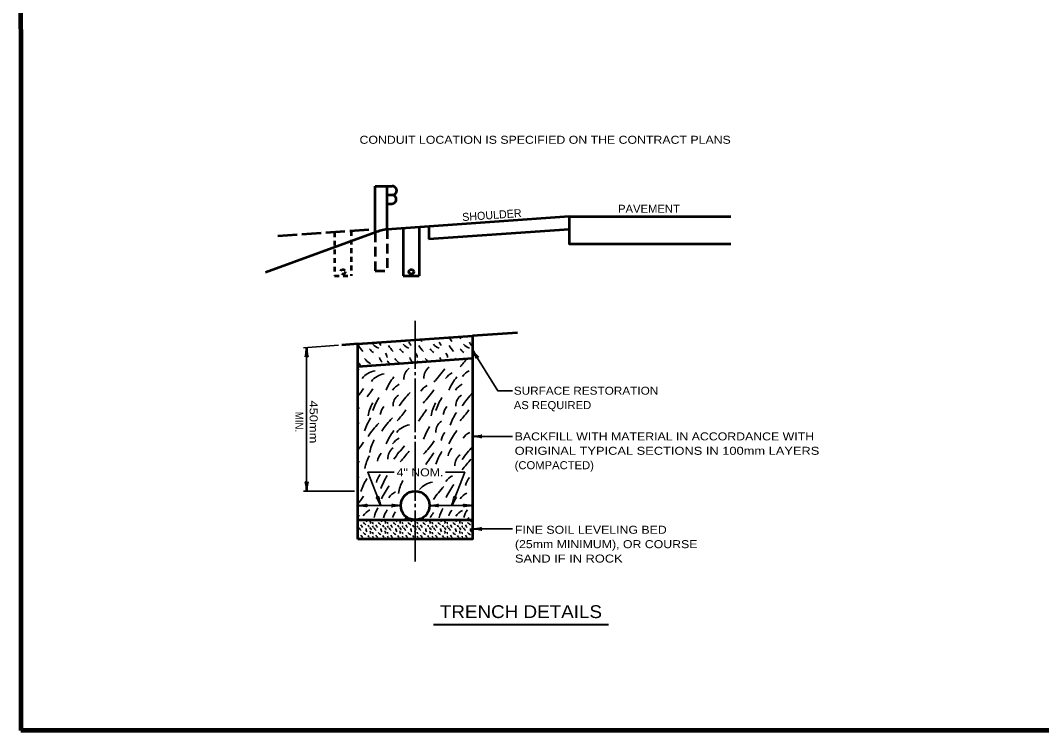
# Model space of a CAD drawing. Extents: x -50 to 806, y -9 to 535.
# Drawn here: x 7.5 to 390.3, y 2.8 to 269 of the extents above; entities that cross this region are included whole.
import ezdxf
from ezdxf.enums import TextEntityAlignment as Align

# ---------------------------------------------------------------- set-up
doc = ezdxf.new("R2010")
doc.units = 0
doc.header["$LTSCALE"] = 1.2
for name, pattern in [('LONG_DASHED', [7.5, 6, -1.5]), ('MEDIUM_DASHED', [4.5, 3, -1.5]), ('SHORT_DASHED', [2.7, 1.5, -1.2])]:
    doc.linetypes.add(name, pattern=pattern)
doc.layers.add('1', color=7, linetype='Continuous', lineweight=35)

msp = doc.modelspace()

# ---------------------------------------------------------------- linework, layer by layer
at = {"layer": '1', "lineweight": 53}
for p, q in [((140.511, 189.479), (140.511, 206.879)), ((140.511, 206.879), (146.811, 206.879)), ((145.011, 203.579), (146.811, 203.579)), ((145.011, 200.279), (146.811, 200.279)), ((213.244, 195.451), (273.844, 195.451)), ((157.011, 191.519), (157.011, 173.279)), ((160.611, 191.77), (160.611, 186.97)), ((140.511, 189.479), (99.352, 174.499)), ((151.011, 191.099), (151.011, 173.279)), ((213.244, 190.651), (160.611, 186.97)), ((151.011, 173.279), (157.011, 173.279)), ((133.917, 147.736), (177.012, 150.749)), ((193.771, 151.921), (177.012, 150.749)), ((177.012, 150.749), (177.012, 142.329)), ((133.917, 147.736), (127.932, 147.317)), ((133.917, 139.315), (133.917, 147.736))]:
    msp.add_line(p, q, dxfattribs=at)
at = {"layer": '1', "linetype": 'LONG_DASHED', "lineweight": 53}
msp.add_line((138.116, 190.512), (103.401, 188.085), dxfattribs=at)
at = {"layer": '1', "linetype": 'SHORT_DASHED', "lineweight": 53}
msp.add_line((131.511, 190.05), (131.511, 173.279), dxfattribs=at)
at = {"layer": '1', "linetype": 'MEDIUM_DASHED', "lineweight": 53}
for p, q in [((140.511, 189.479), (140.511, 175.079)), ((145.011, 190.679), (145.011, 175.079)), ((140.511, 175.079), (145.011, 175.079))]:
    msp.add_line(p, q, dxfattribs=at)
at = {"layer": '1'}
for p, q in [((155.464, 138.357), (155.464, 156.442)), ((126.735, 147.233), (113.567, 146.313)), ((114.767, 92.536), (114.767, 146.397)), ((155.464, 135.957), (155.464, 137.157)), ((155.464, 114.604), (155.464, 134.757)), ((155.464, 112.204), (155.464, 113.404)), ((177.012, 113.049), (192.016, 113.049)), ((155.464, 92.536), (155.464, 111.004)), ((132.717, 92.536), (113.567, 92.536)), ((155.464, 88.936), (155.464, 92.536)), ((150.064, 87.136), (133.917, 87.136)), ((155.464, 86.536), (155.464, 87.736)), ((155.464, 81.736), (155.464, 85.336)), ((160.864, 87.136), (177.012, 87.136)), ((155.464, 66.136), (155.464, 81.736)), ((177.012, 78.369), (192.016, 78.369))]:
    msp.add_line(p, q, dxfattribs=at)
at = {"layer": '1', "lineweight": 40}
msp.add_line((162.365, 42.591), (228.01, 42.591), dxfattribs=at)
at = {"layer": '1', "lineweight": 158}
msp.add_line((799.155, 2.763), (7.555, 2.763), dxfattribs=at)
msp.add_lwpolyline([(799.155, 528.863), (7.455, 528.763), (7.555, 2.763)], dxfattribs=at)
at = {"layer": '1', "lineweight": 53}
for points in [[(213.244, 195.451), (145.011, 190.679), (145.011, 206.879)], [(213.244, 195.451), (213.244, 185.251), (273.844, 185.251)], [(133.917, 81.736), (133.917, 139.315), (177.012, 142.329), (177.012, 81.736)]]:
    msp.add_lwpolyline(points, dxfattribs=at)
at = {"layer": '1', "linetype": 'SHORT_DASHED', "lineweight": 53}
msp.add_lwpolyline([(125.211, 189.609), (125.211, 173.279), (131.511, 173.279)], dxfattribs=at)
at = {"layer": '1'}
for points in [[(177.012, 145.448), (186.417, 130.174), (192.016, 130.174)], [(147.596, 99.63), (137.691, 99.63), (142.547, 87.136)], [(166.855, 99.63), (174.075, 99.63), (169.219, 87.136)]]:
    msp.add_lwpolyline(points, dxfattribs=at)
at = {"layer": '1', "lineweight": 53}
msp.add_lwpolyline([(133.917, 74.536), (133.917, 81.736), (177.012, 81.736), (177.012, 74.536)], close=True, dxfattribs=at)
at = {"layer": '1', "linetype": 'SHORT_DASHED', "lineweight": 53}
msp.add_circle((128.361, 174.779), 0.9, dxfattribs=at)
at = {"layer": '1', "lineweight": 53}
for centre, radius in [((154.011, 174.779), 0.9), ((155.464, 87.136), 5.4)]:
    msp.add_circle(centre, radius, dxfattribs=at)
for centre, radius, start, end in [((146.885, 205.229), 1.652, 267.42897, 92.57103), ((146.736, 201.929), 1.652, 267.42897, 92.57103), ((146.313, 176.757), 13.983, 95.34535, 114.51748)]:
    msp.add_arc(centre, radius, start, end, dxfattribs=at)
at = {"layer": '1'}
for centre, radius, start, end in [((135.888, 133.103), 26.988, 35.21542, 37.08999), ((147.216, 133.103), 26.988, 35.21542, 39.11596), ((176.211, 155.733), 6.947, 230.36768, 239.42983), ((180.068, 153.138), 4.111, 215.86437, 221.98733), ((142.651, 152), 9.765, 210.01676, 226.2782), ((142.186, 148.278), 4.499, 212.31381, 237.6655), ((143.133, 150.65), 4.662, 221.18175, 253.32925), ((137.217, 144.628), 5.908, 24.88286, 38.30577), ((153.979, 152), 9.765, 210.01676, 226.2782), ((153.514, 148.278), 4.499, 212.31381, 237.6655), ((154.461, 150.65), 4.662, 221.18175, 253.32925), ((148.545, 144.628), 5.908, 24.88286, 39.11285), ((165.307, 152), 9.765, 210.01676, 226.2782), ((164.842, 148.278), 4.499, 212.31381, 237.6655), ((165.789, 150.65), 4.662, 221.18175, 253.32925), ((159.873, 144.628), 5.908, 24.88286, 39.11285), ((176.635, 152), 9.765, 210.01676, 226.2782), ((176.17, 148.278), 4.499, 212.31381, 237.6655), ((177.117, 150.65), 4.662, 221.18175, 253.32925), ((171.201, 144.628), 5.908, 24.88286, 39.11285), ((142.227, 146.277), 6.947, 214.79584, 239.42983), ((146.084, 143.682), 4.111, 194.9284, 222.27877), ((142.459, 142.692), 2.446, 358.18251, 41.77121), ((153.555, 146.277), 6.947, 214.79584, 237.37734), ((157.412, 143.682), 4.111, 194.9284, 222.27877), ((153.787, 142.692), 2.446, 358.18251, 41.77121), ((164.883, 146.277), 6.947, 214.79584, 227.53781), ((168.74, 143.682), 4.111, 194.9284, 211.96003), ((165.115, 142.692), 2.446, 358.18251, 41.77121), ((176.211, 146.277), 6.947, 214.79584, 219.10556), ((146.654, 163.184), 35.169, 316.85332, 323.32436), ((180.068, 143.682), 4.111, 194.9284, 200.0611), ((113.232, 123.647), 26.988, 35.71347, 39.96501), ((135.438, 130.94), 7.331, 97.86047, 101.97732), ((124.56, 123.647), 26.988, 37.70729, 41.08213), ((156.083, 134.668), 4.834, 125.55617, 183.03926), ((135.888, 123.647), 26.988, 39.74853, 41.08213), ((163.56, 135.035), 4.834, 125.55617, 183.03926), ((174.709, 138.996), 13.418, 170.36149, 171.43197), ((137.106, 158.231), 35.483, 315.74458, 326.0875), ((172.55, 140.141), 6.727, 167.85392, 168.69132), ((141.424, 130.346), 7.331, 97.86047, 142.43933), ((144.842, 129.231), 7.331, 97.86047, 142.43933), ((170.483, 118.385), 28.609, 143.51724, 155.10041), ((172.362, 130.996), 6.628, 116.78814, 145.60117), ((194.075, 118.385), 28.609, 143.51724, 155.10041), ((178.676, 131.768), 6.628, 116.78814, 145.60117), ((182.622, 130.94), 7.331, 139.93842, 142.43933), ((106.695, 150.848), 35.483, 320.10204, 326.0875), ((110.186, 150.7), 35.483, 320.10204, 326.0875), ((152.484, 126.686), 6.628, 116.78814, 145.60117), ((163.002, 126.24), 6.628, 116.78814, 145.60117), ((133.035, 150.328), 35.483, 315.74458, 326.0875), ((176.076, 126.686), 6.628, 116.78814, 145.60117), ((169.626, 111.257), 32.207, 149.42797, 158.94436), ((151.998, 124.636), 4.834, 125.55617, 183.03926), ((180.074, 103.819), 36.934, 135.94755, 145.88313), ((193.218, 111.257), 32.207, 149.42797, 158.94436), ((175.59, 124.636), 4.834, 125.55617, 183.03926), ((203.666, 103.819), 36.934, 136.19292, 145.88313), ((-19.32, 225.043), 184.032, 326.37338, 326.66613), ((151.117, 118.812), 13.418, 149.50579, 171.43197), ((148.958, 119.957), 6.727, 140.62862, 168.69132), ((123.062, 143), 35.169, 316.85332, 325.30832), ((5.906, 224.225), 184.032, 325.03164, 326.66613), ((174.709, 118.812), 13.418, 149.50579, 171.43197), ((172.55, 119.957), 6.727, 140.62862, 168.69132), ((146.654, 143), 35.169, 316.85332, 325.30832), ((166.506, 103.586), 32.207, 149.42797, 158.94436), ((173.485, 94.317), 36.934, 135.94755, 145.88313), ((168.087, 114.81), 4.834, 125.55617, 183.03926), ((198.641, 105.684), 32.207, 149.42797, 158.94436), ((135.438, 110.756), 7.331, 97.86047, 101.97732), ((168.359, 92.311), 36.934, 135.94755, 145.88313), ((170.483, 98.201), 28.609, 143.51724, 155.10041), ((154.35, 110.088), 7.331, 97.86047, 142.43933), ((188.612, 100.39), 32.207, 149.42797, 158.94436), ((194.075, 98.201), 28.609, 143.51724, 155.10041), ((182.622, 110.756), 7.331, 139.93842, 142.43933), ((151.711, 105.019), 13.418, 149.50579, 171.43197), ((152.484, 106.502), 6.628, 116.78814, 145.60117), ((133.184, 131.185), 35.483, 315.74458, 326.0875), ((171.807, 110.251), 6.727, 140.62862, 168.69132), ((178.887, 108.643), 6.628, 116.78814, 145.60117), ((106.695, 130.664), 35.483, 320.10204, 326.0875), ((150.026, 104.83), 4.834, 125.55617, 183.03926), ((178.06, 83.803), 36.934, 135.94755, 145.88313), ((124.237, 127.558), 35.169, 316.85332, 325.30832), ((193.218, 91.073), 32.207, 149.42797, 158.94436), ((174.396, 104.39), 6.727, 140.62862, 168.69132), ((203.666, 83.635), 36.934, 136.19292, 145.88313), ((-19.32, 204.859), 184.032, 326.37338, 326.66613), ((149.894, 98.975), 13.418, 149.50579, 171.43197), ((147.909, 102.459), 6.727, 140.62862, 168.69132), ((8.656, 208.02), 184.032, 325.03164, 326.66613), ((175.17, 102.227), 4.834, 125.55617, 183.03926), ((147.367, 124.578), 35.169, 316.85332, 325.30832), ((135.438, 90.572), 7.331, 97.86047, 101.97732), ((165.097, 80.882), 32.207, 149.42797, 158.94436), ((147.531, 94.443), 6.727, 140.62862, 168.69132), ((172.701, 81.999), 32.207, 149.42797, 158.94436), ((162.444, 89.697), 13.418, 149.50579, 171.43197), ((162.914, 88.619), 7.331, 97.86047, 142.43933), ((172.475, 92.365), 6.628, 116.78814, 145.60117), ((180.989, 93.37), 6.727, 140.62862, 168.69132), ((168.763, 77.556), 28.609, 143.51724, 155.10041), ((151.015, 86.318), 6.628, 116.78814, 145.60117), ((192.928, 68.728), 36.934, 136.19292, 145.88313), ((193.026, 78.059), 28.609, 143.51724, 155.10041), ((182.622, 90.572), 7.331, 139.93842, 142.43933), ((106.695, 110.48), 35.483, 320.10204, 326.0875), ((177.796, 85.857), 6.628, 116.78814, 145.60117), ((141.415, 79.556), 6.628, 116.78814, 145.60117), ((153.048, 79.41), 13.418, 149.50579, 165.79857), ((150.221, 81.196), 6.727, 140.62862, 168.69132), ((153.341, 80.481), 6.727, 140.62862, 161.39272), ((8.589, 185.627), 184.032, 325.98885, 326.66613), ((177.457, 79.261), 13.418, 149.50579, 165.79857), ((174.407, 81.075), 6.727, 140.62862, 161.39272), ((176.224, 79.407), 6.628, 116.78814, 145.60117), ((180.307, 81.27), 6.727, 140.62862, 168.69132), ((-19.32, 184.675), 184.032, 326.37338, 326.66613), ((134.174, 80.728), 0.313, 214.78265, 277.12922), ((137.018, 83.766), 2.829, 225.86486, 230.55554), ((139.425, 83.834), 4.574, 221.45311, 238.05569), ((139.921, 82.496), 2.912, 195.13344, 210.03985), ((138.124, 80.823), 0.598, 317.34474, 61.57588), ((139.766, 80.728), 0.313, 150.23947, 277.12922), ((142.61, 83.766), 2.829, 225.86486, 230.55554), ((145.017, 83.834), 4.574, 221.45311, 238.05569), ((145.513, 82.496), 2.912, 195.13344, 210.03985), ((143.716, 80.823), 0.598, 317.34474, 61.57588), ((145.358, 80.728), 0.313, 150.23947, 277.12922), ((148.202, 83.766), 2.829, 225.86486, 230.55554), ((150.609, 83.834), 4.574, 221.45311, 238.05569), ((151.105, 82.496), 2.912, 195.13344, 210.03985), ((149.308, 80.823), 0.598, 317.34474, 61.57588), ((150.95, 80.728), 0.313, 150.23947, 277.12922), ((123.062, 102.632), 35.169, 323.54678, 325.30832), ((153.794, 83.766), 2.829, 225.86486, 230.55554), ((156.201, 83.834), 4.574, 221.45311, 238.05569), ((156.697, 82.496), 2.912, 195.13344, 210.03985), ((154.9, 80.823), 0.598, 317.34474, 61.57588), ((156.542, 80.728), 0.313, 150.23947, 277.12922), ((159.386, 83.766), 2.829, 225.86486, 230.55554), ((161.793, 83.834), 4.574, 221.45311, 238.05569), ((162.289, 82.496), 2.912, 195.13344, 210.03985), ((160.492, 80.823), 0.598, 317.34474, 61.57588), ((162.134, 80.728), 0.313, 150.23947, 277.12922), ((164.978, 83.766), 2.829, 225.86486, 230.55554), ((167.385, 83.834), 4.574, 221.45311, 238.05569), ((167.881, 82.496), 2.912, 195.13344, 210.03985), ((166.084, 80.823), 0.598, 317.34474, 61.57588), ((167.726, 80.728), 0.313, 150.23947, 277.12922), ((170.57, 83.766), 2.829, 225.86486, 230.55554), ((172.977, 83.834), 4.574, 221.45311, 238.05569), ((173.473, 82.496), 2.912, 195.13344, 210.03985), ((171.676, 80.823), 0.598, 317.34474, 61.57588), ((173.318, 80.728), 0.313, 150.23947, 277.12922), ((176.162, 83.766), 2.829, 225.86486, 230.55554), ((146.654, 102.632), 35.169, 323.54678, 325.30832), ((178.569, 83.834), 4.574, 221.45311, 238.05569), ((179.065, 82.496), 2.912, 195.13344, 210.03985), ((134.51, 79.474), 0.608, 192.65873, 240.71511), ((134.174, 76.936), 0.313, 214.78265, 277.12922), ((137.018, 79.974), 2.829, 204.56614, 230.55554), ((138.423, 81.388), 3.612, 204.77096, 222.58913), ((139.425, 80.042), 4.574, 221.45311, 238.05569), ((139.921, 78.704), 2.912, 182.72927, 210.03985), ((138.531, 79.791), 0.746, 185.54013, 248.19074), ((138.124, 77.031), 0.598, 317.34474, 61.57588), ((139.181, 78.753), 0.576, 159.67517, 270.27989), ((139.766, 76.936), 0.313, 150.23947, 277.12922), ((140.102, 79.474), 0.608, 178.77007, 240.71511), ((142.61, 79.974), 2.829, 204.56614, 230.55554), ((144.015, 81.388), 3.612, 204.77096, 222.58913), ((145.017, 80.042), 4.574, 221.45311, 238.05569), ((145.513, 78.704), 2.912, 182.72927, 210.03985), ((144.123, 79.791), 0.746, 185.54013, 248.19074), ((143.716, 77.031), 0.598, 317.34474, 61.57588), ((144.773, 78.753), 0.576, 159.67517, 270.27989), ((145.358, 76.936), 0.313, 150.23947, 277.12922), ((145.694, 79.474), 0.608, 178.77007, 240.71511), ((148.202, 79.974), 2.829, 204.56614, 230.55554), ((149.607, 81.388), 3.612, 204.77096, 222.58913), ((150.609, 80.042), 4.574, 221.45311, 238.05569), ((151.105, 78.704), 2.912, 182.72927, 210.03985), ((149.715, 79.791), 0.746, 185.54013, 248.19074), ((149.308, 77.031), 0.598, 317.34474, 61.57588), ((150.365, 78.753), 0.576, 159.67517, 270.27989), ((150.95, 76.936), 0.313, 150.23947, 277.12922), ((151.286, 79.474), 0.608, 178.77007, 240.71511), ((153.794, 79.974), 2.829, 204.56614, 230.55554), ((155.199, 81.388), 3.612, 204.77096, 222.58913), ((156.201, 80.042), 4.574, 221.45311, 238.05569), ((156.697, 78.704), 2.912, 182.72927, 210.03985), ((155.307, 79.791), 0.746, 185.54013, 248.19074), ((154.9, 77.031), 0.598, 317.34474, 61.57588), ((155.957, 78.753), 0.576, 159.67517, 270.27989), ((156.542, 76.936), 0.313, 150.23947, 277.12922), ((156.878, 79.474), 0.608, 178.77007, 240.71511), ((159.386, 79.974), 2.829, 204.56614, 230.55554), ((160.791, 81.388), 3.612, 204.77096, 222.58913), ((161.793, 80.042), 4.574, 221.45311, 238.05569), ((162.289, 78.704), 2.912, 182.72927, 210.03985), ((160.899, 79.791), 0.746, 185.54013, 248.19074), ((160.492, 77.031), 0.598, 317.34474, 61.57588), ((161.549, 78.753), 0.576, 159.67517, 270.27989), ((162.134, 76.936), 0.313, 150.23947, 277.12922), ((162.47, 79.474), 0.608, 178.77007, 240.71511), ((164.978, 79.974), 2.829, 204.56614, 230.55554), ((166.383, 81.388), 3.612, 204.77096, 222.58913), ((167.385, 80.042), 4.574, 221.45311, 238.05569), ((167.881, 78.704), 2.912, 182.72927, 210.03985), ((166.491, 79.791), 0.746, 185.54013, 248.19074), ((166.084, 77.031), 0.598, 317.34474, 61.57588), ((167.141, 78.753), 0.576, 159.67517, 270.27989), ((167.726, 76.936), 0.313, 150.23947, 277.12922), ((168.062, 79.474), 0.608, 178.77007, 240.71511), ((170.57, 79.974), 2.829, 204.56614, 230.55554), ((171.975, 81.388), 3.612, 204.77096, 222.58913), ((172.977, 80.042), 4.574, 221.45311, 238.05569), ((173.473, 78.704), 2.912, 182.72927, 210.03985), ((172.083, 79.791), 0.746, 185.54013, 248.19074), ((171.676, 77.031), 0.598, 317.34474, 61.57588), ((172.733, 78.753), 0.576, 159.67517, 270.27989), ((173.318, 76.936), 0.313, 150.23947, 277.12922), ((173.654, 79.474), 0.608, 178.77007, 240.71511), ((176.162, 79.974), 2.829, 204.56614, 230.55554), ((177.567, 81.388), 3.612, 204.77096, 222.58913), ((178.569, 80.042), 4.574, 221.45311, 238.05569), ((179.065, 78.704), 2.912, 182.72927, 210.03985), ((177.675, 79.791), 0.746, 185.54013, 207.30991), ((134.51, 75.682), 0.608, 192.65873, 240.71511), ((137.018, 76.182), 2.829, 204.56614, 215.58842), ((138.423, 77.596), 3.612, 204.77096, 222.58913), ((139.921, 74.912), 2.912, 182.72927, 187.42205), ((138.531, 75.999), 0.746, 185.54013, 248.19074), ((139.181, 74.961), 0.576, 159.67517, 227.62772), ((140.102, 75.682), 0.608, 178.77007, 240.71511), ((142.61, 76.182), 2.829, 204.56614, 215.58842), ((144.015, 77.596), 3.612, 204.77096, 222.58913), ((145.513, 74.912), 2.912, 182.72927, 187.42205), ((144.123, 75.999), 0.746, 185.54013, 248.19074), ((144.773, 74.961), 0.576, 159.67517, 227.62772), ((145.694, 75.682), 0.608, 178.77007, 240.71511), ((148.202, 76.182), 2.829, 204.56614, 215.58842), ((149.607, 77.596), 3.612, 204.77096, 222.58913), ((151.105, 74.912), 2.912, 182.72927, 187.42205), ((149.715, 75.999), 0.746, 185.54013, 248.19074), ((150.365, 74.961), 0.576, 159.67517, 227.62772), ((151.286, 75.682), 0.608, 178.77007, 240.71511), ((153.794, 76.182), 2.829, 204.56614, 215.58842), ((155.199, 77.596), 3.612, 204.77096, 222.58913), ((156.697, 74.912), 2.912, 182.72927, 187.42205), ((155.307, 75.999), 0.746, 185.54013, 248.19074), ((155.957, 74.961), 0.576, 159.67517, 227.62772), ((156.878, 75.682), 0.608, 178.77007, 240.71511), ((159.386, 76.182), 2.829, 204.56614, 215.58842), ((160.791, 77.596), 3.612, 204.77096, 222.58913), ((162.289, 74.912), 2.912, 182.72927, 187.42205), ((160.899, 75.999), 0.746, 185.54013, 248.19074), ((161.549, 74.961), 0.576, 159.67517, 227.62772), ((162.47, 75.682), 0.608, 178.77007, 240.71511), ((164.978, 76.182), 2.829, 204.56614, 215.58842), ((166.383, 77.596), 3.612, 204.77096, 222.58913), ((167.881, 74.912), 2.912, 182.72927, 187.42205), ((166.491, 75.999), 0.746, 185.54013, 248.19074), ((167.141, 74.961), 0.576, 159.67517, 227.62772), ((168.062, 75.682), 0.608, 178.77007, 240.71511), ((170.57, 76.182), 2.829, 204.56614, 215.58842), ((171.975, 77.596), 3.612, 204.77096, 222.58913), ((173.473, 74.912), 2.912, 182.72927, 187.42205), ((172.083, 75.999), 0.746, 185.54013, 248.19074), ((172.733, 74.961), 0.576, 159.67517, 227.62772), ((173.654, 75.682), 0.608, 178.77007, 240.71511), ((176.162, 76.182), 2.829, 204.56614, 215.58842), ((177.567, 77.596), 3.612, 204.77096, 222.58913), ((179.065, 74.912), 2.912, 182.72927, 187.42205), ((177.675, 75.999), 0.746, 185.54013, 207.30991)]:
    msp.add_arc(centre, radius, start, end, dxfattribs=at)
at = {"layer": '1', "lineweight": 40}
for centre, major_axis, ratio, start_param, end_param in [((114.513, 145.052), (0.211, 2.108), 0.07063, 3.1407148, 5.41811), ((115.098, 145.087), (-0.187, 2.143), 0.122415, 0.8963533, 3.1415927), ((177.501, 144.17), (0.926, -1.905), 0.07063, 6.2823074, 8.5597026), ((177.501, 144.17), (0.926, -1.905), 0.07063, 6.2823074, 8.5597026), ((177.981, 144.507), (-1.283, 1.726), 0.122415, 0.8963533, 3.1415927), ((177.981, 144.507), (-1.283, 1.726), 0.122415, 0.8963533, 3.1415927), ((178.356, 112.795), (-2.108, 0.211), 0.07063, 3.1407148, 5.41811), ((178.356, 112.795), (-2.108, 0.211), 0.07063, 3.1407148, 5.41811), ((178.321, 113.381), (-2.143, -0.187), 0.122415, 0.8963533, 3.1415927), ((178.321, 113.381), (-2.143, -0.187), 0.122415, 0.8963533, 3.1415927), ((114.435, 93.845), (0.187, -2.143), 0.122415, 0.8963533, 3.1415927), ((115.021, 93.88), (-0.211, -2.108), 0.07063, 3.1407148, 5.41811), ((141.823, 88.297), (0.96, -1.888), 0.07063, 0.8650754, 3.1424706), ((142.381, 88.476), (0.602, -2.065), 0.122415, 3.1415927, 5.386832), ((169.384, 88.476), (-0.602, -2.065), 0.122415, 0.8963533, 3.1415927), ((169.942, 88.297), (-0.96, -1.888), 0.07063, 3.1407148, 5.41811), ((135.226, 87.467), (-2.143, -0.187), 0.122415, 0.8963533, 3.1415927), ((135.226, 87.467), (-2.143, -0.187), 0.122415, 0.8963533, 3.1415927), ((135.262, 86.882), (-2.108, 0.211), 0.07063, 3.1407148, 5.41811), ((135.262, 86.882), (-2.108, 0.211), 0.07063, 3.1407148, 5.41811), ((148.755, 86.804), (2.143, 0.187), 0.122415, 0.8963533, 3.1415927), ((148.755, 86.804), (2.143, 0.187), 0.122415, 0.8963533, 3.1415927), ((148.72, 87.39), (2.108, -0.211), 0.07063, 3.1407148, 5.41811), ((148.72, 87.39), (2.108, -0.211), 0.07063, 3.1407148, 5.41811), ((162.209, 86.882), (-2.108, 0.211), 0.07063, 3.1407148, 5.41811), ((162.209, 86.882), (-2.108, 0.211), 0.07063, 3.1407148, 5.41811), ((162.174, 87.467), (-2.143, -0.187), 0.122415, 0.8963533, 3.1415927), ((162.174, 87.467), (-2.143, -0.187), 0.122415, 0.8963533, 3.1415927), ((175.702, 86.804), (2.143, 0.187), 0.122415, 0.8963533, 3.1415927), ((175.667, 87.39), (2.108, -0.211), 0.07063, 3.1407148, 5.41811), ((178.356, 78.115), (-2.108, 0.211), 0.07063, 3.1407148, 5.41811), ((178.356, 78.115), (-2.108, 0.211), 0.07063, 3.1407148, 5.41811), ((178.321, 78.701), (-2.143, -0.187), 0.122415, 0.8963533, 3.1415927), ((178.321, 78.701), (-2.143, -0.187), 0.122415, 0.8963533, 3.1415927)]:
    msp.add_ellipse(centre, major_axis=major_axis, ratio=ratio, start_param=start_param, end_param=end_param, dxfattribs=at)

# ---------------------------------------------------------------- texts
at = {"layer": '1'}
for s, height, width, p in [('CONDUIT LOCATION IS SPECIFIED ON THE CONTRACT PLANS', 3, 1.15, (134.604, 222.762)), ('PAVEMENT', 3, 1.05, (231.542, 196.891)), ('SURFACE RESTORATION', 3, 1.1, (192.446, 128.682)), ('AS REQUIRED', 3, 1.05, (192.446, 123.282)), ('BACKFILL WITH MATERIAL IN ACCORDANCE WITH', 3, 1.15, (192.769, 111.557)), ('ORIGINAL TYPICAL SECTIONS IN 100mm LAYERS', 3, 1.2, (192.769, 106.157)), ('(COMPACTED)', 3, 1.05, (192.769, 100.757)), ('4" NOM.', 3, 1.15, (148.518, 98.079)), ('FINE SOIL LEVELING BED', 3, 1.15, (192.877, 76.554)), ('(25mm MINIMUM), OR COURSE', 3, 1.15, (192.877, 71.154)), ('SAND IF IN ROCK', 3, 1.2, (192.877, 65.754)), ('TRENCH DETAILS', 4.8, 1.1, (164.715, 44.942))]:
    msp.add_text(s, height=height, dxfattribs=dict(at, width=width)).set_placement(p)
msp.add_text('SHOULDER', height=3, rotation=4, dxfattribs=at).set_placement((173.206, 193.778))
for s, width, p in [('450mm', 1.2, (115.901, 118.476)), ('MIN.', 0.9, (110.501, 118.476))]:
    msp.add_text(s, height=3, rotation=270, dxfattribs=dict(at, width=width)).set_placement(p, align=Align.CENTER)

doc.saveas('drawing.dxf')
